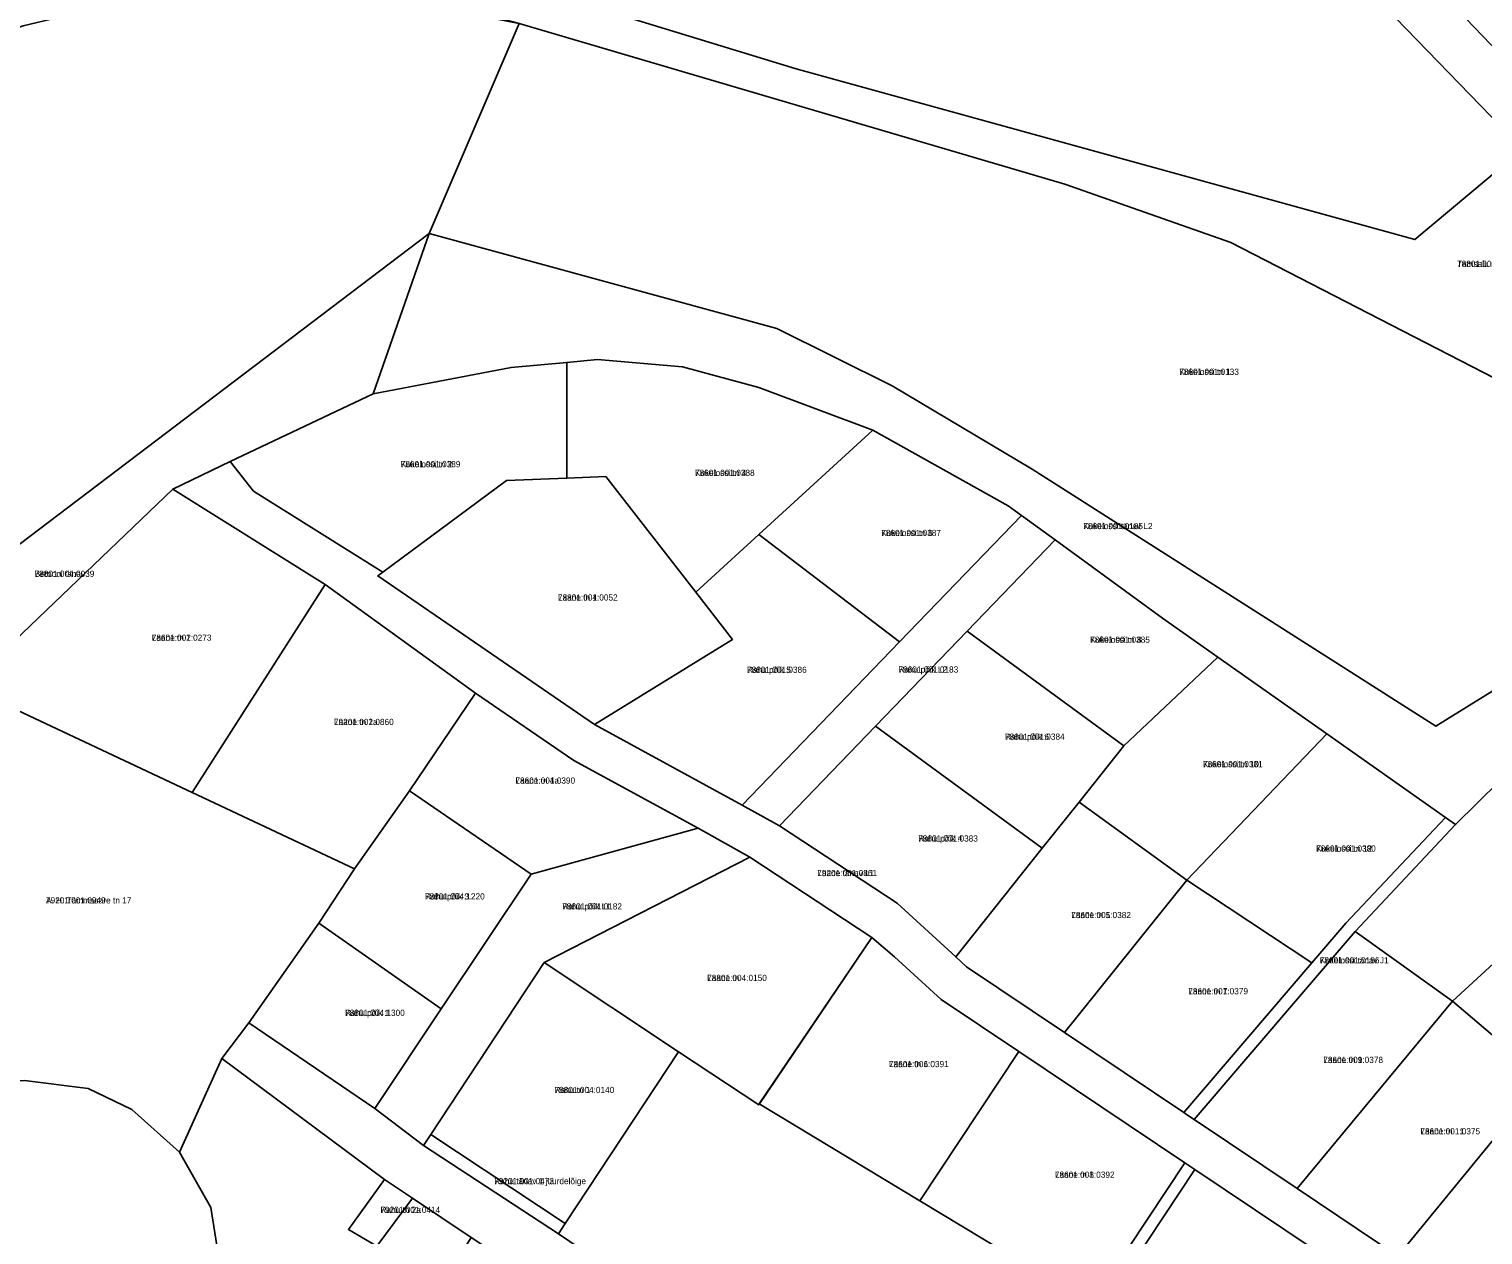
# Model space of a CAD drawing. Extents: x 587616 to 632239, y 6547421 to 6574977.
# Drawn here: x 620040.8 to 620393.8, y 6559918.3 to 6560210.9 of the extents above; entities that cross this region are included whole.
import ezdxf

# ---------------------------------------------------------------- set-up
doc = ezdxf.new("R2010")
doc.units = 0
for name, color, linetype in [('L_AADRESS', 7, 'Continuous'), ('PIIR', 7, 'Continuous'), ('TUNNUS', 7, 'Continuous')]:
    doc.layers.add(name, color=color, linetype=linetype)

msp = doc.modelspace()

# ---------------------------------------------------------------- linework, layer by layer
at = {"layer": 'PIIR'}
for points in [[(620463.7, 6560136.43), (620455.05, 6560128.16), (620403.54, 6560181.71), (620267.1, 6560322.44), (620259.83, 6560337.37), (620265.72, 6560342.45)], [(620126.21, 6560291.87), (620267.1, 6560322.44), (620403.54, 6560181.71), (620377.33, 6560159.78), (620227.11, 6560201.27), (620148.06, 6560225.43), (620139.35, 6560227.36)], [(620516.39, 6560063.19), (620452.52, 6560097.42), (620332.58, 6560159.09), (620292.35, 6560173.28), (620159.79, 6560212.22), (620117.72, 6560223.71), (620097.15, 6560229.33), (620069.55, 6560231.95), (620071.34, 6560243.15), (620139.35, 6560227.36), (620148.06, 6560225.43), (620227.11, 6560201.27), (620377.33, 6560159.78), (620403.54, 6560181.71), (620455.05, 6560128.16)], [(620159.79, 6560212.22), (620137.95, 6560161.24), (620010.12, 6560064.48), (619910.98, 6560107.26), (619921.72, 6560124.73), (619934.84, 6560143.61), (619942.28, 6560152.76), (619946.94, 6560157.54), (619964.09, 6560172.25), (619983.91, 6560187.4), (619994.16, 6560194.03), (620004.53, 6560199.2), (620011.97, 6560202.32), (620027.59, 6560207.94), (620039.39, 6560211.71), (620047.52, 6560213.6), (620055.55, 6560214.89), (620063.43, 6560215.58), (620088.57, 6560216.85), (620110.08, 6560217.39), (620134.12, 6560216.91), (620141.9, 6560215.71)], [(620159.79, 6560212.22), (620292.35, 6560173.28), (620332.58, 6560159.09), (620452.52, 6560097.42), (620407.24, 6560059.25), (620397.91, 6560051.38), (620382.37, 6560041.7), (620284.35, 6560104.05), (620250.4, 6560124.34), (620222.37, 6560138.23), (620137.95, 6560161.24)], [(620137.95, 6560161.24), (620124.39, 6560122.37), (620089.62, 6560105.94), (620075.68, 6560099.26), (620025.61, 6560051.33), (620014.82, 6560042.03), (620005.15, 6560031.16), (619995.58, 6560015.29), (619989.86, 6559999.44), (619969.98, 6559833.99), (619959.37, 6559818.56), (619946.36, 6559798.13), (619972.87, 6560036.01), (619991.59, 6560050.19), (620010.12, 6560064.48)], [(620137.95, 6560161.24), (620222.37, 6560138.23), (620250.4, 6560124.34), (620284.35, 6560104.05), (620382.37, 6560041.7), (620397.91, 6560051.38), (620407.24, 6560059.25), (620419.49, 6560049.08), (620408.65, 6560038.96), (620387.21, 6560017.83), (620384.74, 6560019.57), (620355.92, 6560039.86), (620329.45, 6560058.47), (620316.06, 6560067.92), (620289.94, 6560086.94), (620281.78, 6560092.88), (620278.57, 6560095.21), (620245.72, 6560113.52), (620218, 6560123.89), (620199.48, 6560128.92), (620178.85, 6560130.66), (620171.38, 6560129.98), (620157.86, 6560128.76), (620124.39, 6560122.37)], [(620089.62, 6560105.94), (620124.39, 6560122.37), (620157.86, 6560128.76), (620171.38, 6560129.98), (620171.38, 6560101.93), (620156.71, 6560101.37), (620126.75, 6560079.12), (620095.32, 6560098.77)], [(620245.72, 6560113.52), (620218.04, 6560088.23), (620202.7, 6560074.22), (620180.83, 6560102.29), (620171.38, 6560101.93), (620171.38, 6560129.98), (620178.85, 6560130.66), (620199.48, 6560128.92), (620218, 6560123.89)], [(620218.04, 6560088.23), (620245.72, 6560113.52), (620278.57, 6560095.21), (620281.78, 6560092.88), (620252.19, 6560062.19)], [(620025.61, 6560051.33), (620075.68, 6560099.26), (620112.71, 6560076.09), (620080.45, 6560025.61)], [(620180.83, 6560102.29), (620202.7, 6560074.22), (620211.61, 6560062.78), (620178.07, 6560042.1), (620125.47, 6560078.17), (620126.75, 6560079.12), (620156.71, 6560101.37), (620171.38, 6560101.93)], [(620213.93, 6560022.51), (620252.19, 6560062.19), (620281.78, 6560092.88), (620289.94, 6560086.94), (620268.57, 6560064.77), (620246.36, 6560041.73), (620223.03, 6560017.54)], [(620202.7, 6560074.22), (620218.04, 6560088.23), (620252.19, 6560062.19), (620213.93, 6560022.51), (620178.07, 6560042.1), (620211.61, 6560062.78)], [(620268.57, 6560064.77), (620289.94, 6560086.94), (620316.06, 6560067.92), (620329.45, 6560058.47), (620306.65, 6560036.98)], [(620080.45, 6560025.61), (620112.71, 6560076.09), (620149.24, 6560049.72), (620133.21, 6560026.03), (620119.85, 6560007.1)], [(620246.36, 6560041.73), (620268.57, 6560064.77), (620306.65, 6560036.98), (620295.76, 6560023.31), (620286.8, 6560012.08)], [(620329.45, 6560058.47), (620355.92, 6560039.86), (620321.9, 6560004.32), (620295.76, 6560023.31), (620306.65, 6560036.98)], [(620149.24, 6560049.72), (620173.05, 6560033.42), (620203.29, 6560016.95), (620162.73, 6560005.82), (620133.21, 6560026.03)], [(620246.36, 6560041.73), (620286.8, 6560012.08), (620265.82, 6559985.71), (620251.56, 6559998.76), (620223.03, 6560017.54)], [(620321.9, 6560004.32), (620355.92, 6560039.86), (620384.74, 6560019.57), (620360.57, 6559993.88), (620352.32, 6559984.26)], [(620408.65, 6560038.96), (620430.29, 6560015.27), (620386.44, 6559974.98), (620362.8, 6559991.88), (620387.21, 6560017.83)], [(620111.17, 6559993.9), (620119.85, 6560007.1), (620133.21, 6560026.03), (620162.73, 6560005.82), (620140.85, 6559973.12)], [(620295.76, 6560023.31), (620321.9, 6560004.32), (620292.25, 6559967.35), (620268.46, 6559983.29), (620265.82, 6559985.71), (620286.8, 6560012.08)], [(620384.74, 6560019.57), (620387.21, 6560017.83), (620362.8, 6559991.88), (620323.71, 6559946.27), (620321.89, 6559947.52), (620321.2, 6559947.95), (620352.32, 6559984.26), (620360.57, 6559993.88)], [(620203.29, 6560016.95), (620215.81, 6560009.96), (620165.92, 6559984.35), (620138.34, 6559942.62), (620136.62, 6559939.99), (620124.74, 6559948.92), (620140.85, 6559973.12), (620162.73, 6560005.82)], [(620386.44, 6559974.98), (620430.29, 6560015.27), (620451.75, 6559991.77), (620411.47, 6559953.75), (620408.55, 6559956.22)], [(620198.48, 6559962.68), (620165.92, 6559984.35), (620215.81, 6560009.96), (620245.44, 6559990.47), (620217.97, 6559949.8)], [(620321.9, 6560004.32), (620352.32, 6559984.26), (620321.2, 6559947.95), (620292.25, 6559967.35)], [(620140.85, 6559973.12), (620124.74, 6559948.92), (620094.2, 6559969.74), (620111.17, 6559993.9)], [(620245.44, 6559990.47), (620250.92, 6559985.76), (620262.27, 6559975.4), (620281.11, 6559962.78), (620257.08, 6559926.56), (620218.13, 6559950.04)], [(620362.8, 6559991.88), (620386.44, 6559974.98), (620348.76, 6559929.49), (620323.71, 6559946.27)], [(620198.48, 6559962.68), (620170.96, 6559920.99), (620138.34, 6559942.62), (620165.92, 6559984.35)], [(620348.76, 6559929.49), (620386.44, 6559974.98), (620408.55, 6559956.22), (620373.21, 6559913.1)], [(620094.2, 6559969.74), (620124.74, 6559948.92), (620136.62, 6559939.99), (620169.34, 6559918.51), (620288.7, 6559837.89), (620313.69, 6559821.01), (620307.59, 6559810.93), (620254.22, 6559847.49), (620215.97, 6559872.58), (620194.25, 6559887.53), (620171.05, 6559902.56), (620148.16, 6559917.63), (620133.91, 6559927.16), (620127.08, 6559931.73), (620087.58, 6559961.04)], [(620198.48, 6559962.68), (620217.97, 6559949.8), (620218.13, 6559950.04), (620257.08, 6559926.56), (620298.67, 6559901.48), (620321.42, 6559935.77), (620323.91, 6559934.1), (620301.24, 6559899.93), (620321.99, 6559887.37), (620288.7, 6559837.89), (620169.34, 6559918.51), (620170.96, 6559920.99)], [(620281.11, 6559962.78), (620321.42, 6559935.77), (620298.67, 6559901.48), (620257.08, 6559926.56)], [(620148.16, 6559917.63), (620125.73, 6559881.71), (620087.68, 6559907.51), (620084.98, 6559924.95), (620077.35, 6559938.38), (620087.58, 6559961.04), (620127.08, 6559931.73), (620118.35, 6559919.58), (620125.22, 6559915.55), (620133.91, 6559927.16)], [(620032.01, 6559955.16), (620039.68, 6559955.77), (620055.17, 6559953.83), (620065.76, 6559948.71), (620077.35, 6559938.38), (620084.98, 6559924.95), (620087.68, 6559907.51), (620085.58, 6559894.31), (620078.32, 6559880.52), (620066.43, 6559870.43), (620058.55, 6559866.11), (620043.39, 6559862.69), (620028.07, 6559864.77), (620014, 6559871.29), (620002.88, 6559882.36), (619995.19, 6559895.55), (619994.3, 6559911.15), (619997.65, 6559926.28), (620005.32, 6559939.44), (620017.45, 6559949.38)], [(620408.55, 6559956.22), (620411.47, 6559953.75), (620430.67, 6559937.46), (620397.98, 6559897.99), (620383.42, 6559907.82), (620373.21, 6559913.1)], [(620170.96, 6559920.99), (620169.34, 6559918.51), (620136.62, 6559939.99), (620138.34, 6559942.62)], [(620323.91, 6559934.1), (620367.85, 6559904.72), (620345.97, 6559871.14), (620321.99, 6559887.37), (620301.24, 6559899.93)], [(620127.08, 6559931.73), (620133.91, 6559927.16), (620125.22, 6559915.55), (620118.35, 6559919.58)]]:
    msp.add_lwpolyline(points, close=True, dxfattribs=at)
for points in [[(621050.56, 6559528.63), (620810.28, 6559774.58), (620762.62, 6559835.74), (620750.87, 6559850.81), (620735.11, 6559867.2), (620724.04, 6559856.45), (620709.64, 6559871.5), (620712.02, 6559874.05), (620682.78, 6559903.59), (620574.58, 6560015.45), (620537.69, 6560057.37), (620501.69, 6560096.57), (620463.7, 6560136.43), (620265.72, 6560342.45)], [(620367.85, 6559904.72), (620323.91, 6559934.1), (620321.42, 6559935.77), (620281.11, 6559962.78), (620262.27, 6559975.4), (620250.92, 6559985.76), (620245.44, 6559990.47), (620215.81, 6560009.96), (620203.29, 6560016.95), (620173.05, 6560033.42), (620149.24, 6560049.72), (620112.71, 6560076.09), (620075.68, 6560099.26), (620089.62, 6560105.94), (620095.32, 6560098.77), (620126.75, 6560079.12), (620125.47, 6560078.17), (620178.07, 6560042.1), (620213.93, 6560022.51), (620223.03, 6560017.54), (620251.56, 6559998.76), (620265.82, 6559985.71), (620268.46, 6559983.29), (620292.25, 6559967.35), (620321.2, 6559947.95), (620321.89, 6559947.52), (620323.71, 6559946.27), (620348.76, 6559929.49), (620373.21, 6559913.1)], [(620025.61, 6560051.33), (620080.45, 6560025.61), (620119.85, 6560007.1), (620111.17, 6559993.9), (620094.2, 6559969.74), (620087.58, 6559961.04), (620077.35, 6559938.38), (620065.76, 6559948.71), (620055.17, 6559953.83), (620039.68, 6559955.77)]]:
    msp.add_lwpolyline(points, dxfattribs=at)

# ---------------------------------------------------------------- texts
at = {"layer": 'L_AADRESS'}
for s, p in [('Tamsalu raudteejaama harutee', (620387.54, 6560153.17)), ('Kukelossi tn 1', (620320.09, 6560126.96)), ('Kukelossi tn 2', (620131.05, 6560104.55)), ('Kukelossi tn 4', (620202.49, 6560102.44)), ('Kukelossi tn 6', (620247.73, 6560087.86)), ('Kukelossi tänav L2', (620296.77, 6560089.53)), ('Betooni tänav', (620042.16, 6560077.95)), ('Laane tn 1', (620169.23, 6560072.2)), ('Laane tn 2', (620070.6, 6560062.44)), ('Kukelossi tn 8', (620298.46, 6560061.96)), ('Rahu põik 5', (620215.13, 6560054.66)), ('Rahu põik L2', (620251.93, 6560054.72)), ('Laane tn 2a', (620114.85, 6560042)), ('Rahu põik 6', (620277.77, 6560038.42)), ('Kukelossi tn 10', (620325.84, 6560031.75)), ('Laane tn 4a', (620158.91, 6560027.77)), ('Rahu põik 4', (620256.7, 6560013.72)), ('Kukelossi tn 12', (620353.32, 6560011.28)), ('Laane tänav L1', (620232.21, 6560005.33)), ('Rahu põik 3', (620136.95, 6559999.66)), ('A. H. Tammsaare tn 17', (620044.91, 6559998.7)), ('Rahu põik L1', (620170.28, 6559997.24)), ('Laane tn 5', (620293.86, 6559995.14)), ('Kukelossi tänav J1', (620354.21, 6559984.15)), ('Laane tn 4', (620205.46, 6559979.88)), ('Laane tn 7', (620322.29, 6559976.64)), ('Rahu põik 1', (620117.54, 6559971.41)), ('Laane tn 6', (620249.62, 6559958.97)), ('Laane tn 9', (620355.07, 6559959.99)), ('Rahu tn 1', (620168.41, 6559952.69)), ('Laane tn 11', (620378.65, 6559942.66)), ('Laane tn 8', (620289.89, 6559932.13)), ('Rahu tänav 1 juurdelõige', (620153.75, 6559930.57)), ('Rahu tn 2a', (620126.13, 6559923.59))]:
    msp.add_text(s, height=1.5, dxfattribs=at).set_placement(p)
at = {"layer": 'TUNNUS'}
for s, p in [('78801:004:0002', (620387.54, 6560153.17)), ('78601:001:0133', (620320.09, 6560126.96)), ('78601:001:0389', (620131.05, 6560104.55)), ('78601:001:0388', (620202.49, 6560102.44)), ('78601:001:0387', (620247.73, 6560087.86)), ('78601:001:0185', (620296.77, 6560089.53)), ('78801:004:0039', (620042.16, 6560077.95)), ('78801:004:0052', (620169.23, 6560072.2)), ('78601:001:0273', (620070.6, 6560062.44)), ('78601:001:0385', (620298.46, 6560061.96)), ('78601:001:0386', (620215.13, 6560054.66)), ('78601:001:0183', (620251.93, 6560054.72)), ('79201:001:0860', (620114.85, 6560042)), ('78601:001:0384', (620277.77, 6560038.42)), ('78601:001:0381', (620325.84, 6560031.75)), ('78601:001:0390', (620158.91, 6560027.77)), ('78601:001:0383', (620256.7, 6560013.72)), ('78601:001:0380', (620353.32, 6560011.28)), ('79201:001:0861', (620232.21, 6560005.33)), ('78801:004:1220', (620136.95, 6559999.66)), ('79201:001:0949', (620044.91, 6559998.7)), ('78601:001:0182', (620170.28, 6559997.24)), ('78601:001:0382', (620293.86, 6559995.14)), ('78601:001:0186', (620354.21, 6559984.15)), ('78801:004:0150', (620205.46, 6559979.88)), ('78601:001:0379', (620322.29, 6559976.64)), ('78801:004:1300', (620117.54, 6559971.41)), ('78601:001:0391', (620249.62, 6559958.97)), ('78601:001:0378', (620355.07, 6559959.99)), ('78801:004:0140', (620168.41, 6559952.69)), ('78601:001:0375', (620378.65, 6559942.66)), ('78601:001:0392', (620289.89, 6559932.13)), ('79201:001:0473', (620153.75, 6559930.57)), ('79201:001:0414', (620126.13, 6559923.59))]:
    msp.add_text(s, height=1.5, dxfattribs=at).set_placement(p)

doc.saveas('drawing.dxf')
